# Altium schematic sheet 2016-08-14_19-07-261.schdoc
size 346 x 128 mm; SheetNumber: 1; SheetTotal: 1
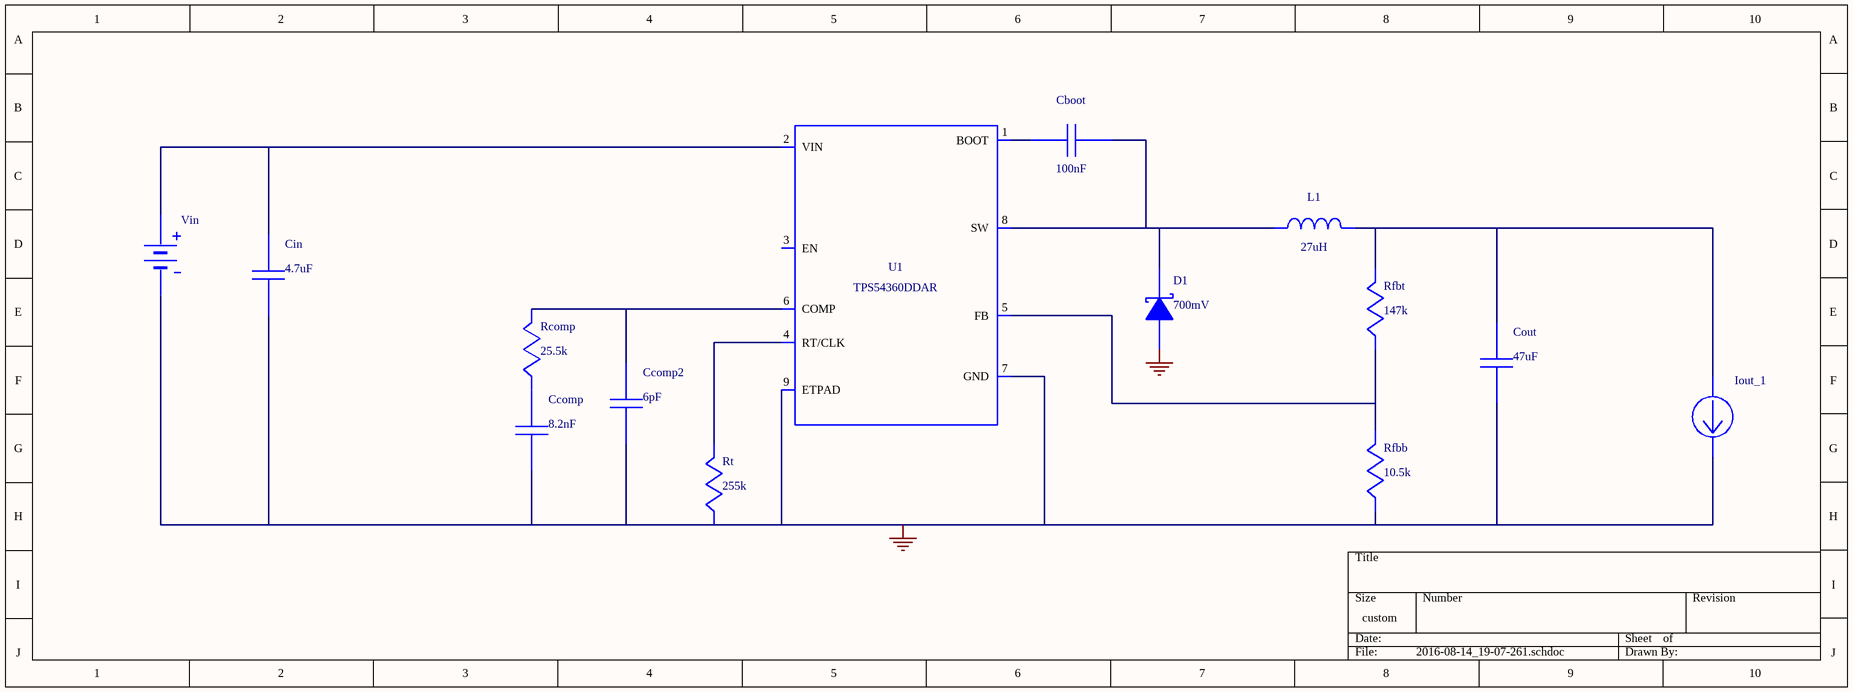
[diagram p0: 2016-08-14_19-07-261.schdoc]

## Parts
Cboot  value 100nF  (hidden comment: GRM155R61A104KA01D)
Ccomp  value 8.2nF  (hidden comment: GRM033R61A822KA01D)
Ccomp2  value 6pF  (hidden comment: CC0805DRNP09BN6R0)
Cin  value 4.7uF  (hidden comment: C3225X7S2A475M200AB)
Cout  value 47uF  (hidden comment: GRM32ER61C476ME15L)
D1  value 700mV  (hidden comment: B560C-13-F)
Iout_1  WB_CURRENT_LOAD  (value not drawn)
L1  value 27uH  (hidden comment: SRR1210-270M)
Rcomp  value 25.5k  (hidden comment: CRCW040225K5FKED)
Rfbb  value 10.5k  (hidden comment: CRCW040210K5FKED)
Rfbt  value 147k  (hidden comment: CRCW0402147KFKED)
Rt  value 255k  (hidden comment: CRCW0402255KFKED)
U1  TPS54360DDAR
Vin  WB_BATTERY  (value not drawn)

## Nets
0: Ccomp.2 Ccomp2.2 Cin.2 Cout.2 D1.2(A) Iout_1.2(-) Rfbb.2 Rt.2 U1.7(GND) U1.9(ETPAD) Vin.2(-)
NetCboot_1: Cboot.1 U1.1(BOOT)
NetCboot_2: Cboot.2 D1.1(K) L1.1 U1.8(SW)
NetCcomp2_1: Ccomp2.1 Rcomp.1 U1.6(COMP)
NetCcomp_1: Ccomp.1 Rcomp.2
NetCin_1: Cin.1 U1.2(VIN) Vin.1(+)
NetCout_1: Cout.1 Iout_1.1(+) L1.2 Rfbt.1
NetRfbb_1: Rfbb.1 Rfbt.2 U1.5(FB)
NetRt_1: Rt.1 U1.4(RT/CLK)

Not connected (* = marked no-connect by the designer): U1 3(EN)

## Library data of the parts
Cboot = GRM155R61A104KA01D: GRM155R61A104KA0; Manufacturer Name: MuRata
Ccomp = GRM033R61A822KA01D: GRM033R61A822KA0; Manufacturer Name: MuRata
Ccomp2 = CC0805DRNP09BN6R0: CC0805DRNP09BN6R; Manufacturer Name: Yageo America
Cin = C3225X7S2A475M200AB: C3225X7S2A475M20; Manufacturer Name: TDK
Cout = GRM32ER61C476ME15L: GRM32ER61C476ME1; Manufacturer Name: MuRata
D1 = B560C-13-F: Manufacturer Name: Diodes Inc.
L1 = SRR1210-270M: Manufacturer Name: Bourns
Rcomp = CRCW040225K5FKED: Manufacturer Name: Vishay-Dale
Rfbb = CRCW040210K5FKED: Manufacturer Name: Vishay-Dale
Rfbt = CRCW0402147KFKED: Manufacturer Name: Vishay-Dale
Rt = CRCW0402255KFKED: Manufacturer Name: Vishay-Dale
U1 = TPS54360DDAR: Manufacturer Name: Texas Instruments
